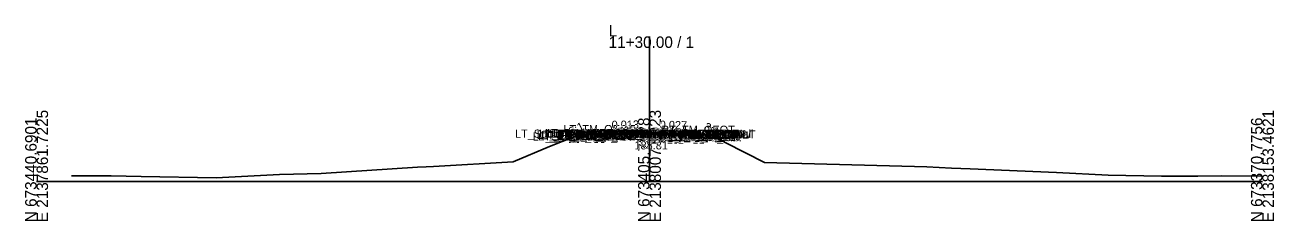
# Model space of a CAD drawing. Extents: x -26 to 5503, y -10 to 7033.
# Drawn here: x 3897.2 to 4202.8, y -9.7 to 38.2 of the extents above; entities that cross this region are included whole.
import ezdxf

# ---------------------------------------------------------------- set-up
doc = ezdxf.new("R2010")
doc.units = 0
for name, color, linetype in [('Default', 7, 'Continuous'), ('Exist Cross Section Cell', 7, 'Continuous'), ('Exist XS Center Line Elevation Label', 7, 'Continuous'), ('Exist XS Ground Line', 7, 'Continuous'), ('Prop CMT Pvmt Course 1', 7, 'Continuous'), ('Prop CMT Pvmt Course 2', 7, 'Continuous'), ('Prop CMT Pvmt Course 2 Wedge', 7, 'Continuous'), ('Prop CMT Pvmt Course 3', 7, 'Continuous'), ('Prop CMT Pvmt Course 3 Wedge', 7, 'Continuous'), ('Prop CMT Pvmt Surface Shoulder', 7, 'Continuous'), ('Prop CMT Pvmt Wedge Surface 1', 7, 'Continuous'), ('Prop CMT Pvmt Wedge Surface 2', 7, 'Continuous'), ('Prop CMT Pvmt Wedge Surface 3', 7, 'Continuous'), ('Prop CMT Shld Paved Course 1', 7, 'Continuous'), ('Prop CMT Shld Paved Course 2', 7, 'Continuous'), ('Prop CMT Shld Paved Course 3', 7, 'Continuous'), ('Prop CMT Slope Grass', 7, 'Continuous'), ('Prop CMT Subgrade Earthwork', 7, 'Continuous'), ('Prop XS Earthwork Shape', 7, 'Continuous'), ('Prop XS SE Text', 7, 'Continuous'), ('Prop XS Side Slope Text', 7, 'Continuous')]:
    doc.layers.add(name, color=color, linetype=linetype)

msp = doc.modelspace()

# ---------------------------------------------------------------- linework, layer by layer
at = {"layer": 'Exist Cross Section Cell'}
for p, q in [((4050, 0), (4050, 35.43)), ((3900, 0), (4050, 0)), ((4050, 0), (4200, 0))]:
    msp.add_line(p, q, dxfattribs=at)
at = {"layer": 'Exist XS Ground Line'}
for p, q in [((4025.49, 8.5), (4031.71, 10.95)), ((4031.71, 10.95), (4037.24, 11.57)), ((4037.24, 11.57), (4037.88, 11.65)), ((4037.88, 11.65), (4047.72, 11.78)), ((4047.72, 11.78), (4050.22, 11.81)), ((4050.22, 11.81), (4061.81, 11.49)), ((4061.81, 11.49), (4062.31, 11.45)), ((4062.31, 11.45), (4065.55, 11.11)), ((4065.55, 11.11), (4068.71, 9.38)), ((4068.71, 9.38), (4078.15, 4.61)), ((4016.62, 4.74), (4025.49, 8.5)), ((3969.66, 1.94), (3993.24, 3.45)), ((3993.24, 3.45), (3995.37, 3.51)), ((3995.37, 3.51), (3997.14, 3.66)), ((3997.14, 3.66), (4016.62, 4.74)), ((4078.15, 4.61), (4117.85, 3.55)), ((4117.85, 3.55), (4123.91, 3.22)), ((4123.91, 3.22), (4128.48, 3.06)), ((4128.48, 3.06), (4149.62, 2.13)), ((3908.58, 1.34), (3915.74, 1.37)), ((3915.74, 1.37), (3918.25, 1.34)), ((3918.25, 1.34), (3925.62, 1.2)), ((3925.62, 1.2), (3943.96, 0.87)), ((3943.96, 0.87), (3959.43, 1.66)), ((3959.43, 1.66), (3969.66, 1.94)), ((4149.62, 2.13), (4162.29, 1.49)), ((4162.29, 1.49), (4175.33, 1.3)), ((4175.33, 1.3), (4184.2, 1.27)), ((4184.2, 1.27), (4190, 1.39)), ((4190, 1.39), (4200, 1.25))]:
    msp.add_line(p, q, dxfattribs=at)
at = {"layer": 'Prop CMT Pvmt Course 1'}
for p, q in [((4050, 11.94), (4037.88, 11.78)), ((4050, 11.82), (4037.88, 11.66)), ((4050, 11.94), (4061.81, 11.62)), ((4050, 11.82), (4061.8, 11.5))]:
    msp.add_line(p, q, dxfattribs=at)
for points in [[(4037.88, 11.78), (4037.88, 11.53)], [(4061.81, 11.62), (4061.81, 11.37)]]:
    msp.add_lwpolyline(points, dxfattribs=at)
at = {"layer": 'Prop CMT Pvmt Course 2'}
for points in [[(4037.88, 11.53), (4037.88, 11.33)], [(4061.81, 11.37), (4061.81, 11.16)]]:
    msp.add_lwpolyline(points, dxfattribs=at)
at = {"layer": 'Prop CMT Pvmt Course 2 Wedge'}
for q in [(4037.88, 11.53), (4061.81, 11.37)]:
    msp.add_line((4050, 11.69), q, dxfattribs=at)
at = {"layer": 'Prop CMT Pvmt Course 3'}
for points in [[(4037.88, 11.33), (4037.88, 10.99)], [(4061.81, 11.16), (4061.81, 10.83)]]:
    msp.add_lwpolyline(points, dxfattribs=at)
at = {"layer": 'Prop CMT Pvmt Course 3 Wedge'}
for q in [(4037.88, 11.33), (4061.81, 11.16)]:
    msp.add_line((4050, 11.48), q, dxfattribs=at)
at = {"layer": 'Prop CMT Pvmt Surface Shoulder'}
for points in [[(4037.88, 11.78), (4037.88, 11.78)], [(4061.81, 11.62), (4061.81, 11.62)]]:
    msp.add_lwpolyline(points, dxfattribs=at)
at = {"layer": 'Prop CMT Pvmt Wedge Surface 1'}
for q in [(4037.88, 11.66), (4061.81, 11.5)]:
    msp.add_line((4050, 11.82), q, dxfattribs=at)
msp.add_lwpolyline([(4037.88, 11.78), (4037.88, 11.78)], dxfattribs=at)
at = {"layer": 'Prop CMT Pvmt Wedge Surface 2'}
for q in [(4037.88, 11.53), (4061.81, 11.37)]:
    msp.add_line((4050, 11.69), q, dxfattribs=at)
for points in [[(4037.88, 11.53), (4037.88, 11.78)], [(4061.81, 11.37), (4061.81, 11.62)]]:
    msp.add_lwpolyline(points, dxfattribs=at)
at = {"layer": 'Prop CMT Pvmt Wedge Surface 3'}
for q in [(4037.88, 11.33), (4061.81, 11.16)]:
    msp.add_line((4050, 11.48), q, dxfattribs=at)
for points in [[(4037.88, 11.33), (4037.88, 11.78)], [(4061.81, 11.16), (4061.81, 11.62)]]:
    msp.add_lwpolyline(points, dxfattribs=at)
at = {"layer": 'Prop CMT Shld Paved Course 1'}
for points in [[(4037.88, 11.78), (4037.63, 11.53)], [(4037.63, 11.53), (4037.88, 11.53)], [(4037.88, 11.78), (4037.88, 11.78)], [(4037.88, 11.53), (4037.88, 11.78)], [(4061.81, 11.62), (4061.81, 11.62)], [(4061.81, 11.62), (4062.06, 11.37)], [(4061.81, 11.37), (4061.81, 11.62)], [(4062.06, 11.37), (4061.81, 11.37)]]:
    msp.add_lwpolyline(points, dxfattribs=at)
at = {"layer": 'Prop CMT Shld Paved Course 2'}
for points in [[(4037.88, 11.53), (4037.63, 11.53), (4037.41, 11.32)], [(4037.41, 11.32), (4037.88, 11.33)], [(4037.88, 11.33), (4037.88, 11.53)], [(4061.81, 11.37), (4062.06, 11.37), (4062.28, 11.15)], [(4061.81, 11.16), (4061.81, 11.37)], [(4062.28, 11.15), (4061.81, 11.16)]]:
    msp.add_lwpolyline(points, dxfattribs=at)
at = {"layer": 'Prop CMT Shld Paved Course 3'}
for points in [[(4037.41, 11.32), (4037.07, 10.98)], [(4037.07, 10.98), (4037.88, 10.99)], [(4037.88, 11.33), (4037.41, 11.32)], [(4037.41, 11.32), (4037.41, 11.32)], [(4037.88, 10.99), (4037.88, 11.33)], [(4061.81, 11.16), (4062.28, 11.15)], [(4061.81, 10.83), (4061.81, 11.16)], [(4062.62, 10.81), (4061.81, 10.83)], [(4062.28, 11.15), (4062.28, 11.15)], [(4062.28, 11.15), (4062.62, 10.81)]]:
    msp.add_lwpolyline(points, dxfattribs=at)
at = {"layer": 'Prop CMT Slope Grass'}
for p, q in [((4033.43, 11.43), (4032.11, 10.98)), ((4037.88, 11.78), (4033.43, 11.43)), ((4061.81, 11.62), (4064.31, 11.42)), ((4064.31, 11.42), (4065.11, 11.16))]:
    msp.add_line(p, q, dxfattribs=at)
at = {"layer": 'Prop CMT Subgrade Earthwork'}
for p, q in [((4037.88, 10.99), (4037.88, 11.78)), ((4061.81, 10.83), (4061.81, 11.62))]:
    msp.add_line(p, q, dxfattribs=at)
for points in [[(4037.07, 10.98), (4036.39, 11.66)], [(4037.88, 10.99), (4037.07, 10.98)], [(4061.81, 10.83), (4062.62, 10.81)], [(4062.62, 10.81), (4063.3, 11.5)]]:
    msp.add_lwpolyline(points, dxfattribs=at)
at = {"layer": 'Prop XS Earthwork Shape'}
for points in [[(4036.56, 11.49), (4036.39, 11.66), (4033.43, 11.43), (4032.13, 10.99)], [(4036.56, 11.49), (4037.24, 11.57), (4037.88, 11.65), (4037.88, 10.99), (4037.07, 10.98)], [(4062.31, 11.45), (4063.16, 11.36), (4062.62, 10.81), (4061.81, 10.83), (4061.81, 11.49)], [(4063.16, 11.36), (4065.11, 11.16), (4064.31, 11.42), (4063.3, 11.5)]]:
    msp.add_lwpolyline(points, close=True, dxfattribs=at)

# ---------------------------------------------------------------- texts
at = {"layer": 'Default'}
for s, height, p in [('LT_Sub_Trench_Out_DLT', 2, (4017.07, 10.66)), ('LT_GS_OS_CTL', 2, (4022.37, 10.38)), ('LT_PV_Sub_Tie_Out', 2, (4022.95, 10.65)), ('LT_PS3_Shelf_Out', 2, (4023.52, 10.31)), ('LT_PV1_OEEOP_Null', 2, (4024.46, 10.78)), ('LT_PV_EG_TestPt3', 2, (4024.85, 10.67)), ('LT_PV_OEEOP_EG', 2, (4025.54, 10.65)), ('LT_PV1_OEEOP_W', 2, (4025.98, 10.66)), ('LT_PV2_OEEOP', 2, (4027.31, 10.53)), ('LT_PV3_OEEOP', 2, (4027.31, 10.32)), ('LT_PS3_OEOP', 2, (4027.77, 10.31)), ('LT_PS2_OEOP', 2, (4027.98, 10.53)), ('LT_PV2_OEOT', 2, (4028.17, 10.53)), ('LT_PV3_OEOT', 2, (4028.17, 10.32)), ('LT_PV1_OEOT', 2, (4028.74, 10.78)), ('LT_PS1_OEOP', 2, (4028.8, 10.78)), ('LT_TM_OEOT', 2, (4028.94, 11.78)), ('LT_PV_EG_TestPt2', 2, (4029.51, 10.73)), ('LT_PV_EG_TestPt1', 2, (4034.75, 10.79)), ('RT_PV_EG_TestPt1', 2, (4037.34, 10.78)), ('PV_EPGL_EG', 2, (4041.24, 10.81)), ('RT_PV_EG_TestPt2', 2, (4041.36, 10.66)), ('PV2_PGL_W', 2, (4042.02, 10.69)), ('PV3_PGL_W', 2, (4042.02, 10.48)), ('PV1_PGL_W', 2, (4042.58, 10.82)), ('RT_Sub_Trench_Out_DLT', 2, (4044.01, 10.49)), ('PV1_PGL', 2, (4044.47, 10.94)), ('RT_PV_EG_TestPt3', 2, (4045.95, 10.53)), ('RT_PV_Sub_Tie_Out', 2, (4046.69, 10.49)), ('RT_PV1_OEEOP_Null', 2, (4048.21, 10.62)), ('RT_PS3_Shelf_Out', 2, (4048.4, 10.15)), ('RT_PV_OEEOP_EG', 2, (4049.29, 10.49)), ('RT_PV1_OEEOP_W', 2, (4049.74, 10.49)), ('RT_PV2_OEEOP', 2, (4051.06, 10.37)), ('RT_PV2_OEOT', 2, (4052.13, 10.36)), ('RT_PS2_OEOP', 2, (4052.44, 10.36)), ('RT_PV1_OEOT', 2, (4052.69, 10.61)), ('RT_PS1_OEOP', 2, (4052.76, 10.61)), ('RT_TM_OEOT', 2, (4052.9, 11.61)), ('RT_GS_OS_CTL', 2, (4053.32, 10.45)), ('RT_Slope_Fill', 2, (4054.93, 10.22)), ('LT_Sub_Trench_Out', 2, (4021.4, 9.97)), ('LT_Slope_Fill', 2, (4022.77, 10.01)), ('LT_Sub_OEEOP', 2, (4027.21, 9.99)), ('LT_Sub_OEOT', 2, (4028.08, 9.99)), ('RT_Sub_Trench_Out', 2, (4046.96, 9.81)), ('RT_Sub_OEEOP', 2, (4050.96, 9.83)), ('RT_PV3_OEEOP', 2, (4051.06, 10.16)), ('RT_Sub_OEOT', 2, (4052.03, 9.82)), ('RT_PV3_OEOT', 2, (4052.13, 10.16)), ('RT_PS3_OEOP', 2, (4052.66, 10.15)), ('-', 0.0001, (3900, 0))]:
    msp.add_text(s, height=height, dxfattribs=at).set_placement(p)
at = {"layer": 'Exist Cross Section Cell'}
for s, p in [('L', (4040, 35.43)), ('11+30.00 / 1', (4040, 32.63))]:
    msp.add_text(s, height=2.8, dxfattribs=at).set_placement(p)
for s, p in [('N 673440.6901', (3900, -10)), ('E 2137861.7225', (3902.8, -10)), ('N 673405.7328', (4050, -10)), ('E 2138007.5923', (4052.8, -10)), ('N 673370.7756', (4200, -10)), ('E 2138153.4621', (4202.8, -10))]:
    msp.add_text(s, height=2.8, rotation=90, dxfattribs=at).set_placement(p)
at = {"layer": 'Exist XS Center Line Elevation Label'}
msp.add_text('188.81', height=2, dxfattribs=at).set_placement((4046.32, 7.81))
at = {"layer": 'Prop XS SE Text'}
for s, rotation, p in [('0.013', 0.7596, (4040.74, 12.82)), ('0.027', 358.4366, (4052.47, 12.87))]:
    msp.add_text(s, height=2, rotation=rotation, dxfattribs=at).set_placement(p)
at = {"layer": 'Prop XS Side Slope Text'}
for rotation, p in [(26.5651, (4030.86, 11.15)), (333.4344, (4063.13, 12.72))]:
    msp.add_text('3:1', height=2, rotation=rotation, dxfattribs=at).set_placement(p)

doc.saveas('drawing.dxf')
